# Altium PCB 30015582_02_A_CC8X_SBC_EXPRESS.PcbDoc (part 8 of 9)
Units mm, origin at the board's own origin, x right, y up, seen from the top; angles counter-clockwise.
Board outline 87 x 63 mm, 6 copper layers (Top Layer-L1, GND Plane-L2, Signal-L3, PWR/Signal-L4, GND Plane-L5, Bottom Layer-L6), stack 1.172 mm thick; 169 components, 171 nets, 693 pads, 391 vias.
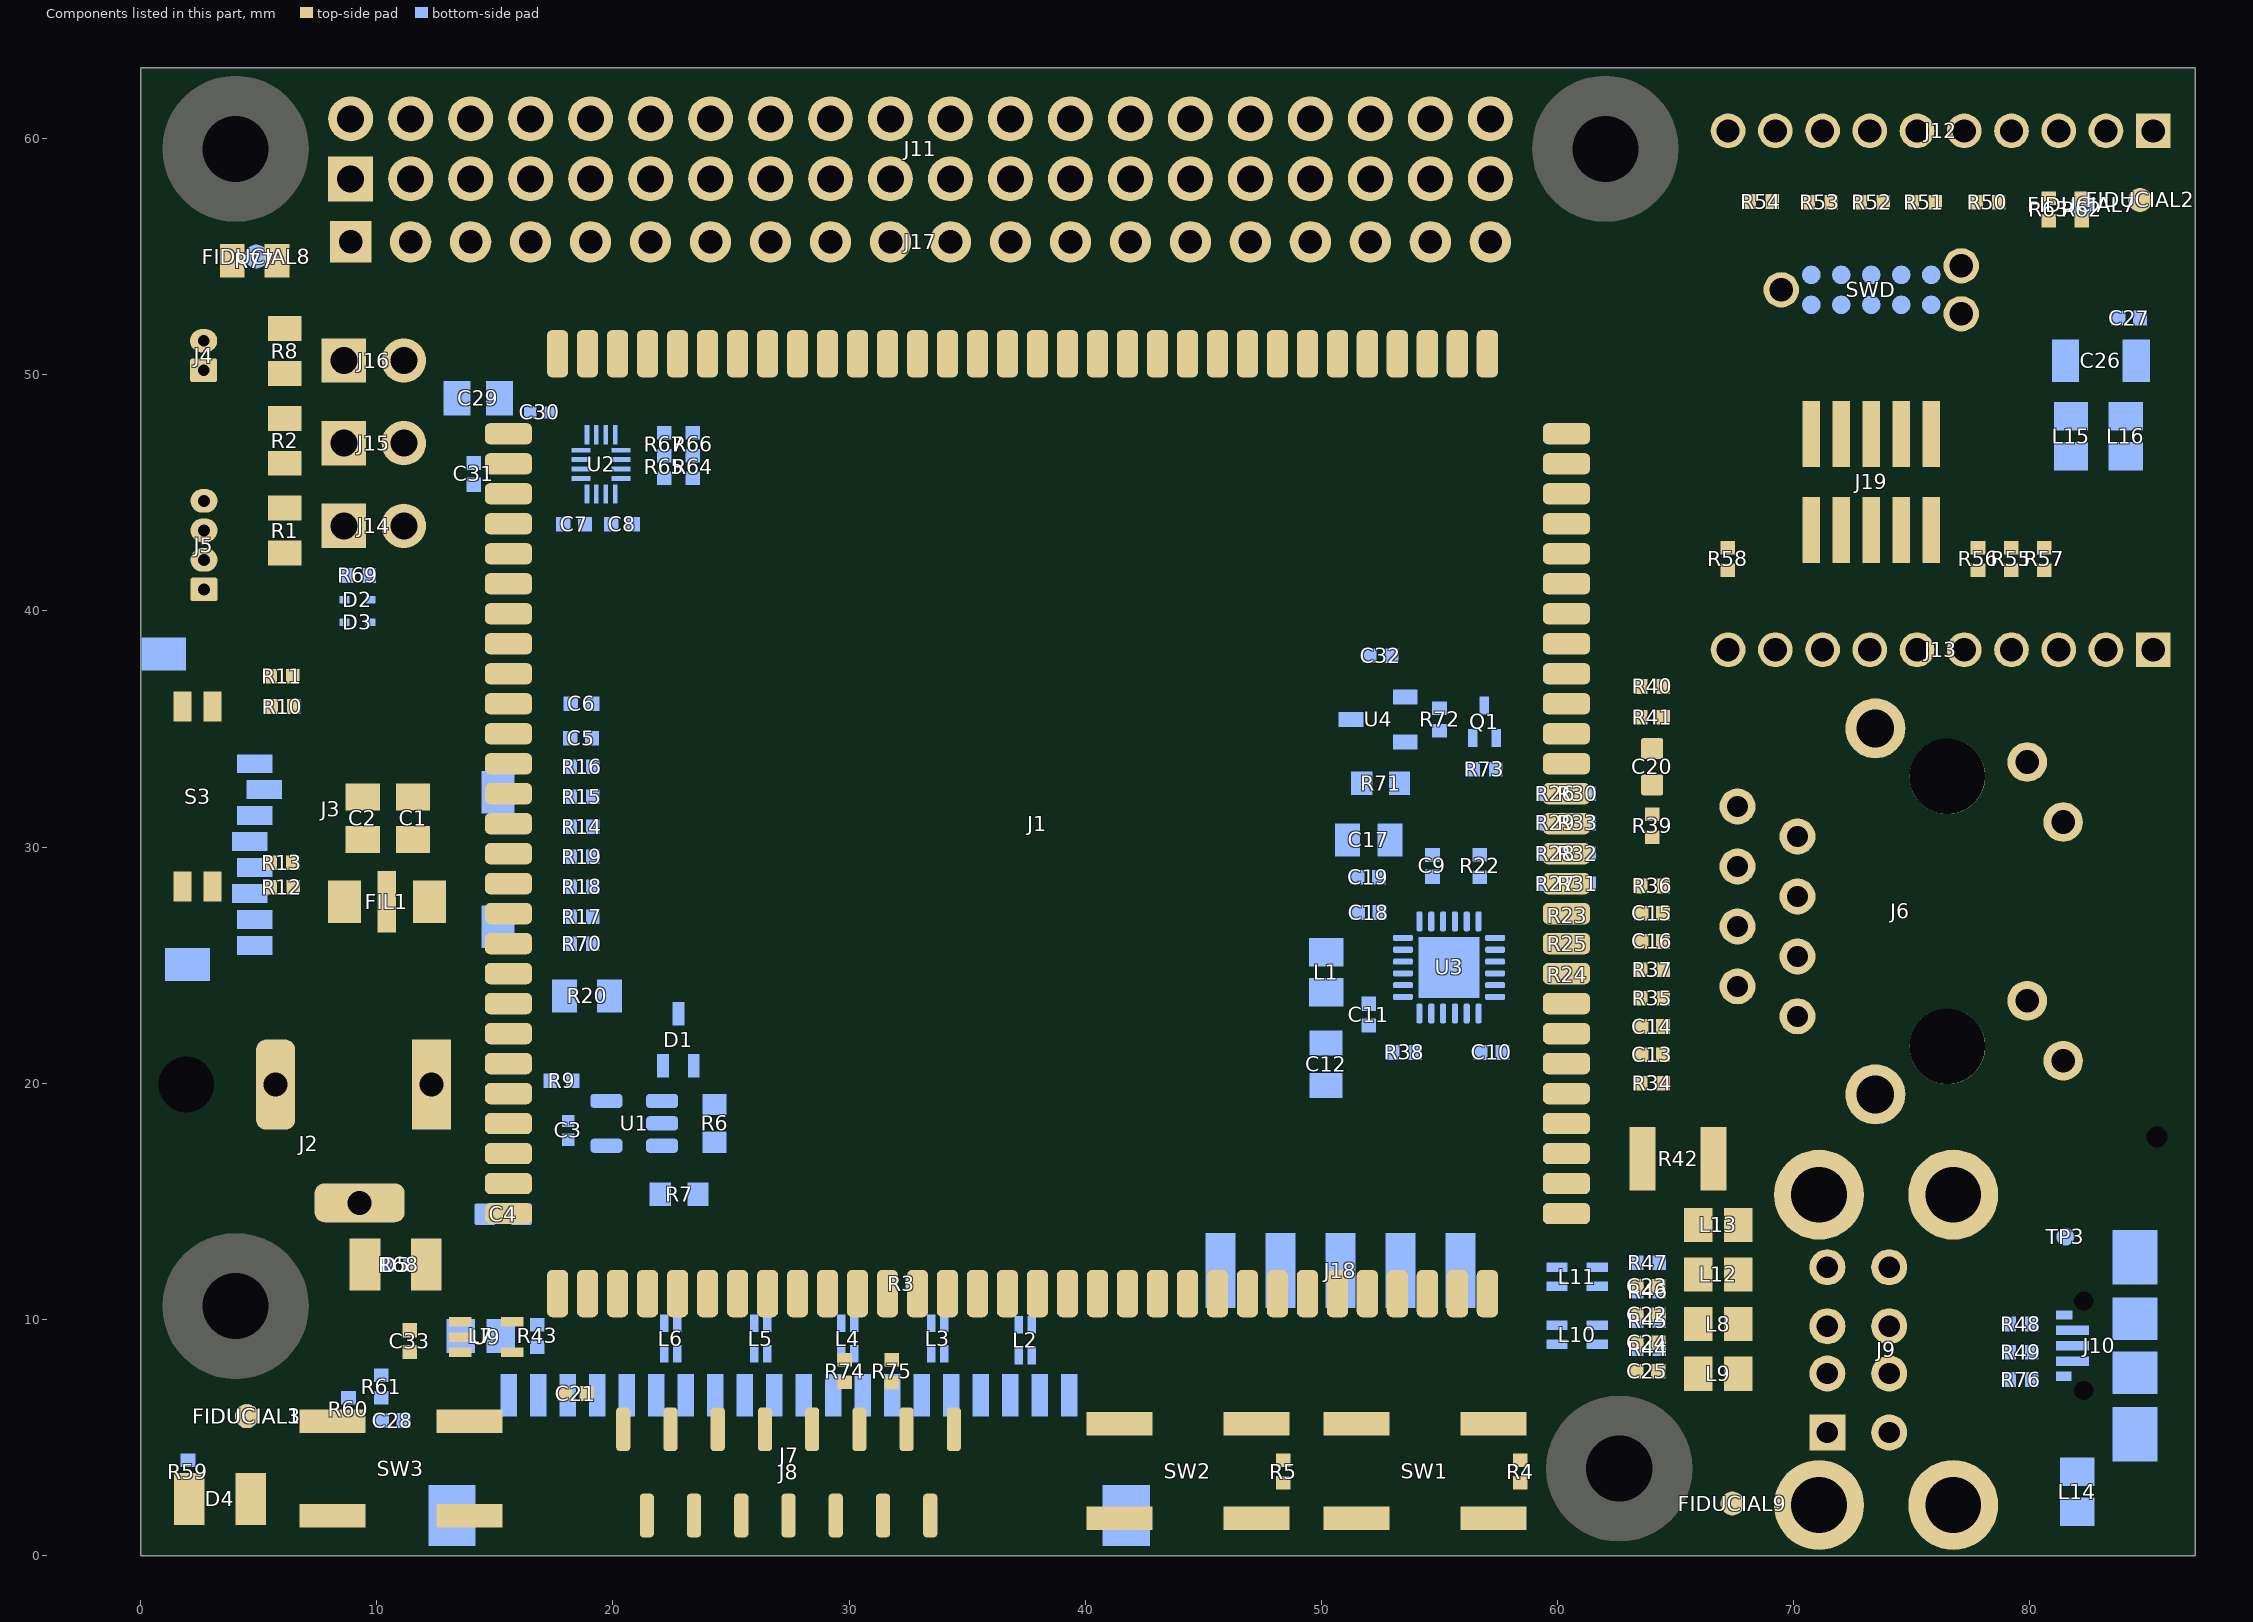
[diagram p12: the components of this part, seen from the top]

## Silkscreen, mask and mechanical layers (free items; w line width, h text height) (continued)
Resistive Material Bottom:
  circle w0.1: c54.7,69.6 r5
  region: 175.78,120.65 211.843,120.65 211.843,120.396 175.78,120.396
  region: 113.371,120.65 149.094,120.65 149.094,120.396 113.371,120.396
  region: 121.517,125.379 165.046,125.379 165.046,125.126 121.517,125.126
  region: 128.857,134.838 173.023,134.838 173.023,134.584 128.857,134.584
  region: 108.28,254.166 156.434,254.166 156.434,253.913 108.28,253.913
  region: 0,34.4 4.9,34.4 8.3,37.8 8.3,49.6 59.6,49.6 64.5,54.5 87,54.5 87,62.9 0,62.9
  region: 63.9,0.3 63.9,3.674 cw(c66.618,3.674) 64.696,5.596 65.4,6.3 65.4,11.074 ccw(c62.682,11.074) 64.604,12.996 64.4,13.2 cw(c65.366,14.166) 64,14.166 64,16.274 cw(c66.718,16.274) 64.796,18.196 64.9,18.3 ccw(c63.21,18.3) 64.405,19.495 62.496,21.404 cw(c64.418,23.326) 61.7,23.326 61.7,32.9 cw(c63.39,32.9) 62.195,34.095 62.5,34.4 62.5,35.234 ccw(c61.134,35.234) 62.1,36.2 62.1,40.074 cw(c64.818,40.074) 62.896,41.996 65.1,44.2 87,44.2 87,14.6 83.7,14.6 83.7,14.19 cw(c81.31,14.19) 83,12.5 81.796,11.296 cw(c79.874,13.218) 79.874,10.5 79.7,10.5 79.7,8.683 ccw(c80.383,8.683) 79.9,8.2 ccw(c80.383,8.683) 80.383,8 80.4,8 cw(c80.4,7.276) 80.912,7.788 82.6,6.1 cw(c81.393,4.893) 83.1,4.893 83.1,4.8 cw(c81.651,3.351) 83.7,3.351 83.7,0.541 cw(c83.359,0.541) 83.6,0.3
  region: 0.7,22.974 cw(c3.418,22.974) 1.496,24.896 2.804,26.204 cw(c4.726,24.282) 4.726,27 6.574,27 cw(c6.574,24.282) 8.496,26.204 8.588,26.112 ccw(c9.1,26.624) 9.1,25.9 ccw(c9.1,26.866) 9.783,26.183 10.1,26.5 cw(c11.066,25.534) 11.066,26.9 13.8,26.9 cw(c13.8,25.21) 14.995,26.405 16.704,24.696 cw(c14.782,22.774) 17.5,22.774 17.5,22.7 cw(c15.81,21.01) 18.2,21.01 18.2,18.926 cw(c15.482,18.926) 17.404,17.004 16.3,15.9 16.3,14.026 cw(c13.582,14.026) 15.504,12.104 14.107,10.707 cw(c12.4,12.414) 12.4,10 12.196,9.796 cw(c10.274,11.718) 10.274,9 8.626,9 cw(c8.626,11.718) 6.704,9.796 1.496,15.004 cw(c3.418,16.926) 0.7,16.926
  text "H" at 85.2,278.446 h4.63
  text "i" at 87.607,278.446 h4.63
  text "E" at 89.38,278.446 h4.63
  text "n" at 91.28,278.446 h4.63
  text "r" at 93.307,278.446 h4.63
  text "i" at 94.658,278.446 h4.63
  text "q" at 95.545,278.446 h4.63
  text "u" at 97.572,278.446 h4.63
  text "e" at 99.599,278.446 h4.63
  text "," at 101.541,278.446 h4.63
  text "I" at 85.2,268.987 h4.63
  text "c" at 87.058,268.987 h4.63
  text "l" at 88.705,268.987 h4.63
  text "e" at 89.591,268.987 h4.63
  text "a" at 91.534,268.987 h4.63
  text "r" at 93.392,268.987 h4.63
  text "l" at 94.743,268.987 h4.63
  text "y" at 95.63,268.987 h4.63
  text "u" at 98.248,268.987 h4.63
  text "n" at 100.274,268.987 h4.63
  text "d" at 102.301,268.987 h4.63
  text "e" at 104.328,268.987 h4.63
  text "r" at 106.27,268.987 h4.63
  text "s" at 107.622,268.987 h4.63
  text "t" at 109.142,268.987 h4.63
  text "a" at 110.451,268.987 h4.63
  text "n" at 112.309,268.987 h4.63
  text "d" at 114.335,268.987 h4.63
  text "y" at 117.207,268.987 h4.63
  text "o" at 118.98,268.987 h4.63
  text "u" at 121.049,268.987 h4.63
  text "r" at 123.076,268.987 h4.63
  text "p" at 125.314,268.987 h4.63
  text "o" at 127.299,268.987 h4.63
  text "i" at 129.368,268.987 h4.63
  text "n" at 130.254,268.987 h4.63
  text "t" at 132.281,268.987 h4.63
  text "a" at 134.477,268.987 h4.63
  text "n" at 136.335,268.987 h4.63
  text "d" at 138.362,268.987 h4.63
  text "w" at 141.233,268.987 h4.63
  text "e" at 144.02,268.987 h4.63
  text "w" at 146.807,268.987 h4.63
  text "i" at 149.594,268.987 h4.63
  text "l" at 150.48,268.987 h4.63
  text "l" at 151.367,268.987 h4.63
  text "s" at 153.14,268.987 h4.63
  text "e" at 154.661,268.987 h4.63
  text "e" at 156.561,268.987 h4.63
  text "w" at 159.39,268.987 h4.63
  text "h" at 162.177,268.987 h4.63
  text "a" at 164.204,268.987 h4.63
  text "t" at 166.019,268.987 h4.63
  text "w" at 168.173,268.987 h4.63
  text "e" at 170.96,268.987 h4.63
  text "c" at 173.789,268.987 h4.63
  text "a" at 175.435,268.987 h4.63
  text "n" at 177.293,268.987 h4.63
  text "d" at 180.165,268.987 h4.63
  text "o" at 182.191,268.987 h4.63
  text "a" at 185.147,268.987 h4.63
  text "s" at 186.963,268.987 h4.63
  text "a" at 189.37,268.987 h4.63
  text "t" at 192.114,268.987 h4.63
  text "r" at 193.381,268.987 h4.63
  text "a" at 194.732,268.987 h4.63
  text "d" at 196.59,268.987 h4.63
  text "e" at 198.617,268.987 h4.63
  text "o" at 200.559,268.987 h4.63
  text "f" at 202.586,268.987 h4.63
  text "f" at 203.769,268.987 h4.63
  text "." at 204.951,268.987 h4.63
  text "H" at 85.2,264.258 h4.63
  text "e" at 87.607,264.258 h4.63
  text "r" at 89.549,264.258 h4.63
  text "e" at 90.9,264.258 h4.63
  text "s" at 93.73,264.258 h4.63
  text "o" at 95.207,264.258 h4.63
  text "m" at 97.234,264.258 h4.63
  text "e" at 100.359,264.258 h4.63
  text "n" at 103.188,264.258 h4.63
  text "o" at 105.173,264.258 h4.63
  text "t" at 107.242,264.258 h4.63
  text "e" at 108.551,264.258 h4.63
  text "s" at 110.451,264.258 h4.63
  text ":" at 111.971,264.258 h4.63
  text "" at 91.564,259.318 h4.59
  text "P" at 97.928,259.318 h4.63
  text "l" at 99.955,259.318 h4.63
  text "e" at 100.841,259.318 h4.63
  text "a" at 102.784,259.318 h4.63
  text "s" at 104.642,259.318 h4.63
  text "e" at 106.12,259.318 h4.63
  text "d" at 108.949,259.318 h4.63
  text "o" at 110.976,259.318 h4.63
  text "n" at 113.045,259.318 h4.63
  text "" at 115.071,259.318 h4.63
  text "t" at 116,259.318 h4.63
  text "c" at 118.196,259.318 h4.63
  text "o" at 119.801,259.318 h4.63
  text "n" at 121.87,259.318 h4.63
  text "s" at 123.896,259.318 h4.63
  text "i" at 125.417,259.318 h4.63
  text "d" at 126.303,259.318 h4.63
  text "e" at 128.33,259.318 h4.63
  text "r" at 130.272,259.318 h4.63
  text "S" at 132.51,259.318 h4.63
  text "W" at 134.242,259.318 h4.63
  text "D" at 137.704,259.318 h4.63
  text "a" at 140.955,259.318 h4.63
  text "s" at 142.813,259.318 h4.63
  text "a" at 145.22,259.318 h4.63
  text "T" at 147.965,259.318 h4.63
  text "H" at 149.865,259.318 h4.63
  text "T" at 152.272,259.318 h4.63
  text "p" at 155.016,259.318 h4.63
  text "a" at 157.043,259.318 h4.63
  text "r" at 158.901,259.318 h4.63
  text "t" at 160.252,259.318 h4.63
  text "." at 161.561,259.318 h4.63
  text "T" at 163.419,259.318 h4.63
  text "h" at 165.319,259.318 h4.63
  text "i" at 167.346,259.318 h4.63
  text "s" at 168.233,259.318 h4.63
  text "s" at 170.598,259.318 h4.63
  text "h" at 172.118,259.318 h4.63
  text "o" at 174.145,259.318 h4.63
  text "u" at 176.214,259.318 h4.63
  text "l" at 178.24,259.318 h4.63
  text "d" at 179.127,259.318 h4.63
  text "b" at 182.041,259.318 h4.63
  text "e" at 184.025,259.318 h4.63
  text "t" at 186.854,259.318 h4.63
  text "h" at 188.163,259.318 h4.63
  text "e" at 190.19,259.318 h4.63
  text "f" at 193.019,259.318 h4.63
  text "o" at 194.159,259.318 h4.63
  text "o" at 196.186,259.318 h4.63
  text "t" at 198.255,259.318 h4.63
  text "p" at 199.564,259.318 h4.63
  text "r" at 201.591,259.318 h4.63
  text "i" at 202.942,259.318 h4.63
  text "n" at 203.829,259.318 h4.63
  text "t" at 205.856,259.318 h4.63
  text "f" at 208.051,259.318 h4.63
  text "o" at 209.192,259.318 h4.63
  text "r" at 211.261,259.318 h4.63
  text "t" at 213.456,259.318 h4.63
  text "h" at 214.765,259.318 h4.63
  text "i" at 216.792,259.318 h4.63
  text "s" at 217.679,259.318 h4.63
  text "k" at 220.086,259.318 h4.63
  text "i" at 221.859,259.318 h4.63
  text "n" at 222.746,259.318 h4.63
  text "d" at 224.773,259.318 h4.63
  text "o" at 227.644,259.318 h4.63
  text "f" at 229.713,259.318 h4.63
  text "c" at 97.928,254.588 h4.63
  text "a" at 99.575,254.588 h4.63
  text "b" at 101.433,254.588 h4.63
  text "l" at 103.459,254.588 h4.63
  text "e" at 104.346,254.588 h4.63
  text ":" at 106.289,254.588 h4.63
  text "h" at 108.28,254.588 h4.63
  text "t" at 110.307,254.588 h4.63
  text "t" at 111.574,254.588 h4.63
  text "p" at 112.882,254.588 h4.63
  text ":" at 114.909,254.588 h4.63
  text "/" at 115.923,254.588 h4.63
  text "/" at 117.443,254.588 h4.63
  text "w" at 118.921,254.588 h4.63
  text "w" at 121.708,254.588 h4.63
  text "w" at 124.452,254.588 h4.63
  text "." at 127.239,254.588 h4.63
  text "t" at 128.21,254.588 h4.63
  text "a" at 129.519,254.588 h4.63
  text "g" at 131.377,254.588 h4.63
  text "-" at 133.312,254.588 h4.63
  text "c" at 134.499,254.588 h4.63
  text "o" at 136.146,254.588 h4.63
  text "n" at 138.215,254.588 h4.63
  text "n" at 140.2,254.588 h4.63
  text "e" at 142.227,254.588 h4.63
  text "c" at 144.169,254.588 h4.63
  text "t" at 145.816,254.588 h4.63
  text "." at 147.125,254.588 h4.63
  text "c" at 148.096,254.588 h4.63
  text "o" at 149.701,254.588 h4.63
  text "m" at 151.77,254.588 h4.63
  text "/" at 154.852,254.588 h4.63
  text "" at 91.564,249.69 h4.59
  text "J" at 97.928,249.69 h4.63
  text "1" at 99.152,249.69 h4.63
  text "4" at 101.137,249.69 h4.63
  text "/" at 103.122,249.69 h4.63
  text "J" at 104.642,249.69 h4.63
  text "1" at 105.824,249.69 h4.63
  text "5" at 107.809,249.69 h4.63
  text "/" at 109.751,249.69 h4.63
  text "J" at 111.271,249.69 h4.63
  text "1" at 112.496,249.69 h4.63
  text "6" at 114.438,249.69 h4.63
  text "s" at 117.309,249.69 h4.63
  text "h" at 118.829,249.69 h4.63
  text "o" at 120.814,249.69 h4.63
  text "u" at 122.883,249.69 h4.63
  text "l" at 124.91,249.69 h4.63
  text "d" at 125.797,249.69 h4.63
  text "a" at 128.71,249.69 h4.63
  text "l" at 130.568,249.69 h4.63
  text "s" at 131.455,249.69 h4.63
  text "o" at 132.975,249.69 h4.63
  text "n" at 135.888,249.69 h4.63
  text "o" at 137.915,249.69 h4.63
  text "t" at 139.942,249.69 h4.63
  text "b" at 142.138,249.69 h4.63
  text "e" at 144.165,249.69 h4.63
  text "c" at 146.994,249.69 h4.63
  text "o" at 148.598,249.69 h4.63
  text "n" at 150.667,249.69 h4.63
  text "s" at 152.694,249.69 h4.63
  text "i" at 154.214,249.69 h4.63
  text "d" at 155.101,249.69 h4.63
  text "e" at 157.128,249.69 h4.63
  text "r" at 159.07,249.69 h4.63
  text "e" at 160.379,249.69 h4.63
  text "d" at 162.321,249.69 h4.63
  text "a" at 165.235,249.69 h4.63
  text "s" at 167.093,249.69 h4.63
  text "T" at 169.5,249.69 h4.63
  text "H" at 171.4,249.69 h4.63
  text "T" at 173.765,249.69 h4.63
  text "p" at 176.551,249.69 h4.63
  text "a" at 178.578,249.69 h4.63
  text "r" at 180.436,249.69 h4.63
  text "t" at 181.787,249.69 h4.63
  text "s" at 183.054,249.69 h4.63
  text "." at 184.574,249.69 h4.63
  text "I" at 186.432,249.69 h4.63
  text "f" at 187.403,249.69 h4.63
  text "t" at 189.472,249.69 h4.63
  text "h" at 190.781,249.69 h4.63
  text "e" at 192.808,249.69 h4.63
  text "y" at 194.75,249.69 h4.63
  text "a" at 197.368,249.69 h4.63
  text "r" at 199.226,249.69 h4.63
  text "e" at 200.578,249.69 h4.63
  text "p" at 203.364,249.69 h4.63
  text "o" at 205.391,249.69 h4.63
  text "p" at 207.46,249.69 h4.63
  text "u" at 209.487,249.69 h4.63
  text "l" at 211.514,249.69 h4.63
  text "a" at 212.401,249.69 h4.63
  text "t" at 214.259,249.69 h4.63
  text "e" at 215.568,249.69 h4.63
  text "d" at 217.51,249.69 h4.63
  text "," at 219.537,249.69 h4.63
  text "i" at 221.352,249.69 h4.63
  text "t" at 222.239,249.69 h4.63
  text "w" at 224.393,249.69 h4.63
  text "i" at 227.18,249.69 h4.63
  text "l" at 228.066,249.69 h4.63
  text "l" at 228.953,249.69 h4.63
  text "a" at 97.928,244.961 h4.63
  text "l" at 99.786,244.961 h4.63
  text "w" at 100.673,244.961 h4.63
  text "a" at 103.459,244.961 h4.63
  text "y" at 105.317,244.961 h4.63
  text "s" at 107.091,244.961 h4.63
  text "b" at 109.455,244.961 h4.63
  text "e" at 111.482,244.961 h4.63
  text "h" at 114.311,244.961 h4.63
  text "a" at 116.338,244.961 h4.63
  text "n" at 118.196,244.961 h4.63
  text "d" at 120.223,244.961 h4.63
  text "s" at 123.136,244.961 h4.63
  text "o" at 124.614,244.961 h4.63
  text "l" at 126.683,244.961 h4.63
  text "d" at 127.57,244.961 h4.63
  text "e" at 129.597,244.961 h4.63
  text "r" at 131.539,244.961 h4.63
  text "i" at 132.89,244.961 h4.63
  text "n" at 133.777,244.961 h4.63
  text "g" at 135.804,244.961 h4.63
  text "." at 137.62,244.961 h4.63
  text "T" at 139.435,244.961 h4.63
  text "h" at 141.336,244.961 h4.63
  text "e" at 143.362,244.961 h4.63
  text "j" at 146.191,244.961 h4.63
  text "u" at 147.12,244.961 h4.63
  text "m" at 149.147,244.961 h4.63
  text "p" at 152.272,244.961 h4.63
  text "e" at 154.256,244.961 h4.63
  text "r" at 156.199,244.961 h4.63
  text "s" at 157.55,244.961 h4.63
  text "a" at 159.957,244.961 h4.63
  text "r" at 161.815,244.961 h4.63
  text "e" at 163.124,244.961 h4.63
  text "t" at 165.953,244.961 h4.63
  text "h" at 167.262,244.961 h4.63
  text "e" at 169.289,244.961 h4.63
  text "r" at 171.189,244.961 h4.63
  text "e" at 172.54,244.961 h4.63
  text "o" at 175.327,244.961 h4.63
  text "n" at 177.396,244.961 h4.63
  text "l" at 179.423,244.961 h4.63
  text "y" at 180.309,244.961 h4.63
  text "f" at 182.927,244.961 h4.63
  text "o" at 184.11,244.961 h4.63
  text "r" at 186.179,244.961 h4.63
  text "d" at 188.417,244.961 h4.63
  text "e" at 190.444,244.961 h4.63
  text "b" at 192.386,244.961 h4.63
  text "u" at 194.413,244.961 h4.63
  text "g" at 196.44,244.961 h4.63
  text "g" at 198.255,244.961 h4.63
  text "i" at 200.071,244.961 h4.63
  text "n" at 200.958,244.961 h4.63
  text "g" at 202.984,244.961 h4.63
  text "p" at 205.687,244.961 h4.63
  text "u" at 207.714,244.961 h4.63
  text "r" at 209.74,244.961 h4.63
  text "p" at 211.092,244.961 h4.63
  text "o" at 213.118,244.961 h4.63
  text "s" at 215.188,244.961 h4.63
  text "e" at 216.665,244.961 h4.63
  text "s" at 218.608,244.961 h4.63
  text "." at 220.128,244.961 h4.63
  text "" at 91.564,240.021 h4.59
  text "C" at 97.928,240.021 h4.63
  text "o" at 99.997,240.021 h4.63
  text "n" at 102.066,240.021 h4.63
  text "c" at 104.093,240.021 h4.63
  text "e" at 105.74,240.021 h4.63
  text "r" at 107.682,240.021 h4.63
  text "n" at 109.033,240.021 h4.63
  text "i" at 111.06,240.021 h4.63
  text "n" at 111.947,240.021 h4.63
  text "g" at 113.974,240.021 h4.63
  text "p" at 116.676,240.021 h4.63
  text "a" at 118.703,240.021 h4.63
  text "r" at 120.561,240.021 h4.63
  text "t" at 121.912,240.021 h4.63
  text "s" at 123.221,240.021 h4.63
  text "b" at 125.585,240.021 h4.63
  text "e" at 127.612,240.021 h4.63
  text "t" at 129.555,240.021 h4.63
  text "w" at 130.821,240.021 h4.63
  text "e" at 133.608,240.021 h4.63
  text "e" at 135.551,240.021 h4.63
  text "n" at 137.493,240.021 h4.63
  text "J" at 140.322,240.021 h4.63
  text "1" at 141.547,240.021 h4.63
  text "2" at 143.531,240.021 h4.63
  text "&" at 146.36,240.021 h4.63
  text "J" at 149.907,240.021 h4.63
  text "1" at 151.132,240.021 h4.63
  text "3" at 153.074,240.021 h4.63
  text "," at 155.059,240.021 h4.63
  text "a" at 156.917,240.021 h4.63
  text "n" at 158.775,240.021 h4.63
  text "d" at 160.801,240.021 h4.63
  text "e" at 163.673,240.021 h4.63
  text "s" at 165.615,240.021 h4.63
  text "p" at 167.135,240.021 h4.63
  text "e" at 169.162,240.021 h4.63
  text "c" at 171.104,240.021 h4.63
  text "i" at 172.751,240.021 h4.63
  text "a" at 173.638,240.021 h4.63
  text "l" at 175.496,240.021 h4.63
  text "l" at 176.382,240.021 h4.63
  text "y" at 177.227,240.021 h4.63
  text "t" at 179.887,240.021 h4.63
  text "h" at 181.196,240.021 h4.63
  text "e" at 183.181,240.021 h4.63
  text "p" at 186.01,240.021 h4.63
  text "a" at 188.037,240.021 h4.63
  text "s" at 189.895,240.021 h4.63
  text "s" at 191.415,240.021 h4.63
  text "i" at 192.935,240.021 h4.63
  text "v" at 193.822,240.021 h4.63
  text "e" at 195.553,240.021 h4.63
  text "," at 197.495,240.021 h4.63
  text "t" at 199.794,240.021 h4.63
  text "h" at 201.103,240.021 h4.63
  text "e" at 203.129,240.021 h4.63
  text "y" at 205.072,240.021 h4.63
  text "c" at 207.69,240.021 h4.63
  text "a" at 209.337,240.021 h4.63
  text "n" at 211.194,240.021 h4.63
  text "b" at 214.108,240.021 h4.63
  text "e" at 216.135,240.021 h4.63
  text "p" at 218.964,240.021 h4.63
  text "l" at 220.991,240.021 h4.63
  text "a" at 221.877,240.021 h4.63
  text "c" at 223.693,240.021 h4.63
  text "e" at 225.298,240.021 h4.63
  text "d" at 227.24,240.021 h4.63
  text "o" at 230.154,240.021 h4.63
  text "n" at 232.223,240.021 h4.63
  text "t" at 235.094,240.021 h4.63
  text "o" at 236.403,240.021 h4.63
  text "p" at 238.472,240.021 h4.63
  text "s" at 97.928,235.291 h4.63
  text "i" at 99.448,235.291 h4.63
  text "d" at 100.335,235.291 h4.63
  text "e" at 102.362,235.291 h4.63
  text "a" at 105.191,235.291 h4.63
  text "p" at 107.049,235.291 h4.63
  text "a" at 109.075,235.291 h4.63
  text "r" at 110.933,235.291 h4.63
  text "t" at 112.285,235.291 h4.63
  text "t" at 114.438,235.291 h4.63
  text "h" at 115.747,235.291 h4.63
  text "e" at 117.774,235.291 h4.63
  text "b" at 120.603,235.291 h4.63
  text "i" at 122.63,235.291 h4.63
  text "g" at 123.516,235.291 h4.63
  text "c" at 126.219,235.291 h4.63
  text "a" at 127.866,235.291 h4.63
  text "p" at 129.724,235.291 h4.63
  text "a" at 132.637,235.291 h4.63
  text "n" at 134.495,235.291 h4.63
  text "d" at 136.522,235.291 h4.63
  text "i" at 139.435,235.291 h4.63
  text "n" at 140.28,235.291 h4.63
  text "d" at 142.307,235.291 h4.63
  text "u" at 144.334,235.291 h4.63
  text "c" at 146.36,235.291 h4.63
  text "t" at 148.007,235.291 h4.63
  text "o" at 149.316,235.291 h4.63
  text "r" at 151.385,235.291 h4.63
  text "s" at 152.736,235.291 h4.63
  text "(" at 155.143,235.291 h4.63
  text "C" at 156.325,235.291 h4.63
  text "2" at 158.352,235.291 h4.63
  text "6" at 160.295,235.291 h4.63
  text "/" at 162.279,235.291 h4.63
  text "L" at 163.757,235.291 h4.63
  text "1" at 165.404,235.291 h4.63
  text "5" at 167.346,235.291 h4.63
  text "/" at 169.331,235.291 h4.63
  text "L" at 170.809,235.291 h4.63
  text "1" at 172.456,235.291 h4.63
  text "6" at 174.398,235.291 h4.63
  text ")" at 176.382,235.291 h4.63
  text "." at 177.565,235.291 h4.63
  text "T" at 179.423,235.291 h4.63
  text "r" at 181.323,235.291 h4.63
  text "y" at 182.632,235.291 h4.63
  text "t" at 185.292,235.291 h4.63
  text "o" at 186.559,235.291 h4.63
  text "p" at 189.515,235.291 h4.63
  text "l" at 191.541,235.291 h4.63
  text "a" at 192.428,235.291 h4.63
  text "c" at 194.286,235.291 h4.63
  text "e" at 195.891,235.291 h4.63
  text "t" at 198.72,235.291 h4.63
  text "h" at 200.029,235.291 h4.63
  text "e" at 202.055,235.291 h4.63
  text "s" at 203.998,235.291 h4.63
  text "e" at 205.476,235.291 h4.63
  text "b" at 208.305,235.291 h4.63
  text "i" at 210.332,235.291 h4.63
  text "g" at 211.218,235.291 h4.63
  text "c" at 213.921,235.291 h4.63
  text "o" at 215.525,235.291 h4.63
  text "m" at 217.552,235.291 h4.63
  text "p" at 220.677,235.291 h4.63
  text "o" at 222.704,235.291 h4.63
  text "n" at 224.73,235.291 h4.63
  text "e" at 226.757,235.291 h4.63
  text "n" at 228.7,235.291 h4.63
  text "t" at 230.726,235.291 h4.63
  text "s" at 232.035,235.291 h4.63
  text "i" at 234.442,235.291 h4.63
  text "n" at 235.329,235.291 h4.63
  text "t" at 97.928,230.562 h4.63
  text "h" at 99.237,230.562 h4.63
  text "e" at 101.264,230.562 h4.63
  text "m" at 104.051,230.562 h4.63
  text "i" at 107.175,230.562 h4.63
  text "d" at 108.062,230.562 h4.63
  text "d" at 110.089,230.562 h4.63
  text "l" at 112.116,230.562 h4.63
  text "e" at 113.002,230.562 h4.63
  text "b" at 115.831,230.562 h4.63
  text "e" at 117.858,230.562 h4.63
  text "t" at 119.801,230.562 h4.63
  text "w" at 121.067,230.562 h4.63
  text "e" at 123.854,230.562 h4.63
  text "e" at 125.754,230.562 h4.63
  text "n" at 127.697,230.562 h4.63
  text "J" at 130.61,230.562 h4.63
  text "1" at 131.835,230.562 h4.63
  text "2" at 133.777,230.562 h4.63
  text "&" at 136.648,230.562 h4.63
  text "J" at 140.111,230.562 h4.63
  text "1" at 141.336,230.562 h4.63
  text "3" at 143.32,230.562 h4.63
  text "." at 145.305,230.562 h4.63
  text "" at 91.564,225.622 h4.59
  text "R" at 97.928,225.622 h4.63
  text "4" at 100.039,225.622 h4.63
  text "2" at 102.024,225.622 h4.63
  text "c" at 104.853,225.622 h4.63
  text "a" at 106.5,225.622 h4.63
  text "n" at 108.358,225.622 h4.63
  text "a" at 111.271,225.622 h4.63
  text "l" at 113.129,225.622 h4.63
  text "s" at 114.016,225.622 h4.63
  text "o" at 115.494,225.622 h4.63
  text "b" at 118.449,225.622 h4.63
  text "e" at 120.476,225.622 h4.63
  text "p" at 123.263,225.622 h4.63
  text "l" at 125.29,225.622 h4.63
  text "a" at 126.177,225.622 h4.63
  text "c" at 128.035,225.622 h4.63
  text "e" at 129.681,225.622 h4.63
  text "d" at 131.624,225.622 h4.63
  text "o" at 134.495,225.622 h4.63
  text "n" at 136.564,225.622 h4.63
  text "t" at 139.478,225.622 h4.63
  text "h" at 140.744,225.622 h4.63
  text "e" at 142.771,225.622 h4.63
  text "T" at 145.6,225.622 h4.63
  text "O" at 147.5,225.622 h4.63
  text "P" at 150.034,225.622 h4.63
  text "s" at 152.947,225.622 h4.63
  text "i" at 154.468,225.622 h4.63
  text "d" at 155.354,225.622 h4.63
  text "e" at 157.381,225.622 h4.63
  text "," at 159.323,225.622 h4.63
  text "I" at 161.139,225.622 h4.63
  text "g" at 162.997,225.622 h4.63
  text "u" at 164.813,225.622 h4.63
  text "e" at 166.84,225.622 h4.63
  text "s" at 168.782,225.622 h4.63
  text "s" at 170.302,225.622 h4.63
  text "." at 171.822,225.622 h4.63
  text "" at 91.564,220.724 h4.59
  text "C" at 97.928,220.724 h4.63
  text "o" at 99.997,220.724 h4.63
  text "n" at 102.066,220.724 h4.63
  text "c" at 104.093,220.724 h4.63
  text "e" at 105.74,220.724 h4.63
  text "r" at 107.682,220.724 h4.63
  text "n" at 109.033,220.724 h4.63
  text "i" at 111.06,220.724 h4.63
  text "n" at 111.947,220.724 h4.63
  text "g" at 113.974,220.724 h4.63
  text "p" at 116.676,220.724 h4.63
  text "a" at 118.703,220.724 h4.63
  text "r" at 120.561,220.724 h4.63
  text "t" at 121.912,220.724 h4.63
  text "s" at 123.221,220.724 h4.63
  text "a" at 125.585,220.724 h4.63
  text "r" at 127.443,220.724 h4.63
  text "o" at 128.795,220.724 h4.63
  text "u" at 130.864,220.724 h4.63
  text "n" at 132.89,220.724 h4.63
  text "d" at 134.917,220.724 h4.63
  text "J" at 137.831,220.724 h4.63
  text "6" at 139.013,220.724 h4.63
  text "," at 140.955,220.724 h4.63
  text "p" at 142.813,220.724 h4.63
  text "l" at 144.84,220.724 h4.63
  text "e" at 145.727,220.724 h4.63
  text "a" at 147.669,220.724 h4.63
  text "s" at 149.527,220.724 h4.63
  text "e" at 151.047,220.724 h4.63
  text "k" at 153.834,220.724 h4.63
  text "e" at 155.608,220.724 h4.63
  text "e" at 157.508,220.724 h4.63
  text "p" at 159.45,220.724 h4.63
  text "C" at 162.364,220.724 h4.63
  text "1" at 164.433,220.724 h4.63
  text "3" at 166.375,220.724 h4.63
  text "/" at 168.36,220.724 h4.63
  text "C" at 169.838,220.724 h4.63
  text "1" at 171.907,220.724 h4.63
  text "4" at 173.849,220.724 h4.63
  text "/" at 175.834,220.724 h4.63
  text "C" at 177.354,220.724 h4.63
  text "1" at 179.38,220.724 h4.63
  text "5" at 181.365,220.724 h4.63
  text "/" at 183.307,220.724 h4.63
  text "C" at 184.828,220.724 h4.63
  text "1" at 186.897,220.724 h4.63
  text "6" at 188.839,220.724 h4.63
  text "o" at 191.668,220.724 h4.63
  text "n" at 193.737,220.724 h4.63
  text "t" at 196.651,220.724 h4.63
  text "h" at 197.96,220.724 h4.63
  text "e" at 199.986,220.724 h4.63
  text "b" at 203.273,220.724 h4.63
  text "o" at 205.299,220.724 h4.63
  text "t" at 207.368,220.724 h4.63
  text "t" at 208.635,220.724 h4.63
  text "o" at 209.944,220.724 h4.63
  text "m" at 211.971,220.724 h4.63
  text "s" at 215.94,220.724 h4.63
  text "i" at 217.46,220.724 h4.63
  text "d" at 218.347,220.724 h4.63
  text "e" at 220.374,220.724 h4.63
  text "." at 222.316,220.724 h4.63
  text "T" at 224.174,220.724 h4.63
  text "h" at 226.032,220.724 h4.63
  text "e" at 228.059,220.724 h4.63
  text "s" at 230.001,220.724 h4.63
  text "e" at 231.521,220.724 h4.63
  text "p" at 97.928,215.995 h4.63
  text "a" at 99.955,215.995 h4.63
  text "r" at 101.813,215.995 h4.63
  text "t" at 103.164,215.995 h4.63
  text "s" at 104.473,215.995 h4.63
  text "w" at 106.88,215.995 h4.63
  text "i" at 109.667,215.995 h4.63
  text "l" at 110.553,215.995 h4.63
  text "l" at 111.44,215.995 h4.63
  text "b" at 113.213,215.995 h4.63
  text "e" at 115.198,215.995 h4.63
  text "m" at 117.985,215.995 h4.63
  text "o" at 121.11,215.995 h4.63
  text "s" at 123.179,215.995 h4.63
  text "t" at 124.657,215.995 h4.63
  text "c" at 126.852,215.995 h4.63
  text "e" at 128.457,215.995 h4.63
  text "r" at 130.399,215.995 h4.63
  text "t" at 131.75,215.995 h4.63
  text "a" at 133.059,215.995 h4.63
  text "i" at 134.917,215.995 h4.63
  text "n" at 135.804,215.995 h4.63
  text "l" at 137.831,215.995 h4.63
  text "y" at 138.718,215.995 h4.63
  text "n" at 141.336,215.995 h4.63
  text "o" at 143.362,215.995 h4.63
  text "t" at 145.431,215.995 h4.63
  text "p" at 147.627,215.995 h4.63
  text "o" at 149.612,215.995 h4.63
  text "p" at 151.681,215.995 h4.63
  text "u" at 153.708,215.995 h4.63
  text "l" at 155.734,215.995 h4.63
  text "a" at 156.621,215.995 h4.63
  text "t" at 158.479,215.995 h4.63
  text "e" at 159.788,215.995 h4.63
  text "d" at 161.73,215.995 h4.63
  text "." at 163.757,215.995 h4.63
  text "K" at 165.573,215.995 h4.63
  text "n" at 167.6,215.995 h4.63
  text "o" at 169.626,215.995 h4.63
  text "w" at 171.653,215.995 h4.63
  text "i" at 174.44,215.995 h4.63
  text "n" at 175.327,215.995 h4.63
  text "g" at 177.354,215.995 h4.63
  text "t" at 180.056,215.995 h4.63
  text "h" at 181.365,215.995 h4.63
  text "i" at 183.35,215.995 h4.63
  text "s" at 184.236,215.995 h4.63
  text "," at 185.757,215.995 h4.63
  text "w" at 187.614,215.995 h4.63
  text "e" at 190.401,215.995 h4.63
  text "s" at 193.188,215.995 h4.63
  text "h" at 194.708,215.995 h4.63
  text "o" at 196.735,215.995 h4.63
  text "u" at 198.804,215.995 h4.63
  text "l" at 200.831,215.995 h4.63
  text "d" at 201.718,215.995 h4.63
  text "b" at 204.631,215.995 h4.63
  text "e" at 206.658,215.995 h4.63
  text "f" at 209.445,215.995 h4.63
  text "i" at 210.627,215.995 h4.63
  text "n" at 211.514,215.995 h4.63
  text "e" at 213.541,215.995 h4.63
  text "w" at 216.328,215.995 h4.63
  text "i" at 219.114,215.995 h4.63
  text "t" at 220.001,215.995 h4.63
  text "h" at 221.31,215.995 h4.63
  text "t" at 224.224,215.995 h4.63
  text "h" at 225.491,215.995 h4.63
  text "e" at 227.517,215.995 h4.63
  text "c" at 97.928,211.265 h4.63
  text "u" at 99.575,211.265 h4.63
  text "r" at 101.602,211.265 h4.63
  text "r" at 102.953,211.265 h4.63
  text "e" at 104.304,211.265 h4.63
  text "n" at 106.246,211.265 h4.63
  text "t" at 108.273,211.265 h4.63
  text "c" at 110.469,211.265 h4.63
  text "l" at 112.116,211.265 h4.63
  text "e" at 112.96,211.265 h4.63
  text "a" at 114.902,211.265 h4.63
  text "r" at 116.76,211.265 h4.63
  text "a" at 118.112,211.265 h4.63
  text "n" at 119.97,211.265 h4.63
  text "c" at 121.996,211.265 h4.63
  text "e" at 123.643,211.265 h4.63
  text "." at 125.585,211.265 h4.63
  text "I" at 127.443,211.265 h4.63
  text "f" at 128.415,211.265 h4.63
  text "y" at 130.441,211.265 h4.63
  text "o" at 132.173,211.265 h4.63
  text "u" at 134.242,211.265 h4.63
  text "c" at 137.155,211.265 h4.63
  text "a" at 138.802,211.265 h4.63
  text "n" at 140.618,211.265 h4.63
  text "m" at 143.531,211.265 h4.63
  text "o" at 146.614,211.265 h4.63
  text "v" at 148.683,211.265 h4.63
  text "e" at 150.414,211.265 h4.63
  text "C" at 153.243,211.265 h4.63
  text "2" at 155.312,211.265 h4.63
  text "0" at 157.254,211.265 h4.63
  text "/" at 159.197,211.265 h4.63
  text "R" at 160.717,211.265 h4.63
  text "3" at 162.828,211.265 h4.63
  text "9" at 164.771,211.265 h4.63
  text "/" at 166.755,211.265 h4.63
  text "R" at 168.233,211.265 h4.63
  text "4" at 170.344,211.265 h4.63
  text "0" at 172.287,211.265 h4.63
  text "/" at 174.271,211.265 h4.63
  text "R" at 175.749,211.265 h4.63
  text "4" at 177.86,211.265 h4.63
  text "1" at 179.803,211.265 h4.63
  text "o" at 182.632,211.265 h4.63
  text "n" at 184.701,211.265 h4.63
  text "T" at 187.614,211.265 h4.63
  text "O" at 189.515,211.265 h4.63
  text "P" at 192.048,211.265 h4.63
  text "s" at 194.962,211.265 h4.63
  text "i" at 196.482,211.265 h4.63
  text "d" at 197.368,211.265 h4.63
  text "e" at 199.353,211.265 h4.63
  text "," at 201.295,211.265 h4.63
  text "t" at 203.153,211.265 h4.63
  text "h" at 204.462,211.265 h4.63
  text "a" at 206.489,211.265 h4.63
  text "t" at 208.305,211.265 h4.63
  text "w" at 210.501,211.265 h4.63
  text "o" at 213.245,211.265 h4.63
  text "u" at 215.314,211.265 h4.63
  text "l" at 217.341,211.265 h4.63
  text "d" at 218.228,211.265 h4.63
  text "b" at 221.141,211.265 h4.63
  text "e" at 223.168,211.265 h4.63
  text "p" at 225.955,211.265 h4.63
  text "e" at 227.982,211.265 h4.63
  text "r" at 229.924,211.265 h4.63
  text "f" at 231.275,211.265 h4.63
  text "e" at 232.458,211.265 h4.63
  text "c" at 234.4,211.265 h4.63
  text "t" at 236.047,211.265 h4.63
  text "." at 237.356,211.265 h4.63
  text "R" at 97.928,206.536 h4.63
  text "4" at 100.039,206.536 h4.63
  text "2" at 102.024,206.536 h4.63
  text "c" at 104.853,206.536 h4.63
  text "o" at 106.5,206.536 h4.63
  text "u" at 108.569,206.536 h4.63
  text "l" at 110.595,206.536 h4.63
  text "d" at 111.482,206.536 h4.63
  text "a" at 114.396,206.536 h4.63
  text "l" at 116.254,206.536 h4.63
  text "s" at 117.098,206.536 h4.63
  text "o" at 118.618,206.536 h4.63
  text "m" at 121.532,206.536 h4.63
  text "o" at 124.614,206.536 h4.63
  text "v" at 126.641,206.536 h4.63
  text "e" at 128.415,206.536 h4.63
  text "t" at 131.244,206.536 h4.63
  text "o" at 132.51,206.536 h4.63
  text "T" at 135.424,206.536 h4.63
  text "O" at 137.324,206.536 h4.63
  text "P" at 139.858,206.536 h4.63
  text "s" at 142.771,206.536 h4.63
  text "i" at 144.291,206.536 h4.63
  text "d" at 145.178,206.536 h4.63
  text "e" at 147.205,206.536 h4.63
  text "." at 149.147,206.536 h4.63
  text "" at 91.564,201.596 h4.59
  text "C" at 97.928,201.596 h4.63
  text "o" at 99.997,201.596 h4.63
  text "n" at 102.066,201.596 h4.63
  text "c" at 104.093,201.596 h4.63
  text "e" at 105.74,201.596 h4.63
  text "r" at 107.682,201.596 h4.63
  text "n" at 109.033,201.596 h4.63
  text "i" at 111.06,201.596 h4.63
  text "n" at 111.947,201.596 h4.63
  text "g" at 113.974,201.596 h4.63
  text "R" at 116.676,201.596 h4.63
  text "4" at 118.745,201.596 h4.63
  text "8" at 120.73,201.596 h4.63
  text "/" at 122.672,201.596 h4.63
  text "R" at 124.192,201.596 h4.63
  text "4" at 126.261,201.596 h4.63
  text "9" at 128.246,201.596 h4.63
  text "a" at 131.075,201.596 h4.63
  text "n" at 132.933,201.596 h4.63
  text "d" at 134.959,201.596 h4.63
  text "R" at 137.873,201.596 h4.63
  text "7" at 139.942,201.596 h4.63
  text "6" at 141.927,201.596 h4.63
  text "," at 143.911,201.596 h4.63
  text "t" at 145.727,201.596 h4.63
  text "r" at 147.036,201.596 h4.63
  text "y" at 148.387,201.596 h4.63
  text "t" at 151.258,201.596 h4.63
  text "o" at 152.525,201.596 h4.63
  text "m" at 155.438,201.596 h4.63
  text "o" at 158.563,201.596 h4.63
  text "v" at 160.59,201.596 h4.63
  text "e" at 162.363,201.596 h4.63
  text "t" at 165.15,201.596 h4.63
  text "h" at 166.459,201.596 h4.63
  text "e" at 168.486,201.596 h4.63
  text "m" at 170.386,201.596 h4.63
  text "a" at 174.397,201.596 h4.63
  text "s" at 176.255,201.596 h4.63
  text "c" at 178.62,201.596 h4.63
  text "l" at 180.267,201.596 h4.63
  text "o" at 181.153,201.596 h4.63
  text "s" at 183.18,201.596 h4.63
  text "e" at 184.7,201.596 h4.63
  text "a" at 187.529,201.596 h4.63
  text "s" at 189.387,201.596 h4.63
  text "p" at 191.794,201.596 h4.63
  text "o" at 193.779,201.596 h4.63
  text "s" at 195.848,201.596 h4.63
  text "s" at 197.368,201.596 h4.63
  text "i" at 198.888,201.596 h4.63
  text "b" at 199.775,201.596 h4.63
  text "l" at 201.802,201.596 h4.63
  text "e" at 202.688,201.596 h4.63
  text "t" at 205.475,201.596 h4.63
  text "o" at 206.784,201.596 h4.63
  text "J" at 209.698,201.596 h4.63
  text "1" at 210.922,201.596 h4.63
  text "0" at 212.865,201.596 h4.63
  text "f" at 215.736,201.596 h4.63
  text "o" at 216.876,201.596 h4.63
  text "r" at 218.945,201.596 h4.63
  text "i" at 221.183,201.596 h4.63
  text "n" at 222.07,201.596 h4.63
  text "c" at 224.096,201.596 h4.63
  text "r" at 225.701,201.596 h4.63
  text "e" at 227.052,201.596 h4.63
  text "a" at 228.995,201.596 h4.63
  text "s" at 230.853,201.596 h4.63
  text "e" at 232.373,201.596 h4.63
  text "t" at 235.16,201.596 h4.63
  text "h" at 236.468,201.596 h4.63
  text "e" at 238.495,201.596 h4.63
  text "c" at 97.928,196.866 h4.63
  text "l" at 99.575,196.866 h4.63
  text "e" at 100.461,196.866 h4.63
  text "a" at 102.404,196.866 h4.63
  text "r" at 104.262,196.866 h4.63
  text "a" at 105.613,196.866 h4.63
  text "n" at 107.471,196.866 h4.63
  text "c" at 109.498,196.866 h4.63
  text "e" at 111.144,196.866 h4.63
  text "w" at 113.931,196.866 h4.63
  text "i" at 116.718,196.866 h4.63
  text "t" at 117.605,196.866 h4.63
  text "h" at 118.914,196.866 h4.63
  text "J" at 121.827,196.866 h4.63
  text "9" at 123.01,196.866 h4.63
  text "." at 124.994,196.866 h4.63
  text "Y" at 126.852,196.866 h4.63
  text "o" at 128.71,196.866 h4.63
  text "u" at 130.779,196.866 h4.63
  text "w" at 133.693,196.866 h4.63
  text "i" at 136.48,196.866 h4.63
  text "l" at 137.366,196.866 h4.63
  text "l" at 138.253,196.866 h4.63
  text "n" at 139.942,196.866 h4.63
  text "o" at 141.969,196.866 h4.63
  text "t" at 144.038,196.866 h4.63
  text "r" at 146.234,196.866 h4.63
  text "e" at 147.585,196.866 h4.63
  text "a" at 149.485,196.866 h4.63
  text "c" at 151.343,196.866 h4.63
  text "h" at 152.99,196.866 h4.63
  text "5" at 155.903,196.866 h4.63
  text "m" at 157.846,196.866 h4.63
  text "m" at 160.928,196.866 h4.63
  text "," at 164.053,196.866 h4.63
  text "b" at 165.911,196.866 h4.63
  text "u" at 167.937,196.866 h4.63
  text "t" at 169.964,196.866 h4.63
  text "t" at 172.118,196.866 h4.63
  text "r" at 173.427,196.866 h4.63
  text "y" at 174.778,196.866 h4.63
  text "t" at 177.396,196.866 h4.63
  text "o" at 178.663,196.866 h4.63
  text "g" at 181.576,196.866 h4.63
  text "a" at 183.392,196.866 h4.63
  text "i" at 185.25,196.866 h4.63
  text "n" at 186.137,196.866 h4.63
  text "a" at 189.05,196.866 h4.63
  text "s" at 190.908,196.866 h4.63
  text "m" at 193.315,196.866 h4.63
  text "u" at 196.44,196.866 h4.63
  text "c" at 198.466,196.866 h4.63
  text "h" at 200.113,196.866 h4.63
  text "a" at 202.984,196.866 h4.63
  text "s" at 204.842,196.866 h4.63
  text "p" at 207.249,196.866 h4.63
  text "o" at 209.276,196.866 h4.63
  text "s" at 211.303,196.866 h4.63
  text "s" at 212.823,196.866 h4.63
  text "i" at 214.343,196.866 h4.63
  text "b" at 215.23,196.866 h4.63
  text "l" at 217.257,196.866 h4.63
  text "e" at 218.143,196.866 h4.63
  text "." at 220.086,196.866 h4.63
  text "" at 91.564,191.926 h4.59
  text "O" at 97.928,191.926 h4.63
  text "n" at 100.504,191.926 h4.63
  text "t" at 103.417,191.926 h4.63
  text "h" at 104.726,191.926 h4.63
  text "e" at 106.753,191.926 h4.63
  text "o" at 109.54,191.926 h4.63
  text "t" at 111.609,191.926 h4.63
  text "h" at 112.918,191.926 h4.63
  text "e" at 114.945,191.926 h4.63
  text "r" at 116.887,191.926 h4.63
  text "s" at 119.083,191.926 h4.63
  text "i" at 120.603,191.926 h4.63
  text "d" at 121.49,191.926 h4.63
  text "e" at 123.516,191.926 h4.63
  text "o" at 126.303,191.926 h4.63
  text "f" at 128.372,191.926 h4.63
  text "t" at 130.399,191.926 h4.63
  text "h" at 131.708,191.926 h4.63
  text "e" at 133.735,191.926 h4.63
  text "U" at 136.564,191.926 h4.63
  text "S" at 139.055,191.926 h4.63
  text "B" at 140.787,191.926 h4.63
  text "c" at 143.785,191.926 h4.63
  text "o" at 145.431,191.926 h4.63
  text "n" at 147.5,191.926 h4.63
  text "n" at 149.527,191.926 h4.63
  text "e" at 151.554,191.926 h4.63
  text "c" at 153.454,191.926 h4.63
  text "t" at 155.101,191.926 h4.63
  text "o" at 156.368,191.926 h4.63
  text "r" at 158.437,191.926 h4.63
  text "(" at 160.675,191.926 h4.63
  text "J" at 161.857,191.926 h4.63
  text "9" at 163.082,191.926 h4.63
  text ")" at 165.024,191.926 h4.63
  text "," at 166.206,191.926 h4.63
  text "c" at 168.064,191.926 h4.63
  text "o" at 169.669,191.926 h4.63
  text "u" at 171.738,191.926 h4.63
  text "l" at 173.765,191.926 h4.63
  text "d" at 174.651,191.926 h4.63
  text "y" at 177.565,191.926 h4.63
  text "o" at 179.296,191.926 h4.63
  text "u" at 181.365,191.926 h4.63
  text "c" at 184.236,191.926 h4.63
  text "h" at 185.883,191.926 h4.63
  text "e" at 187.91,191.926 h4.63
  text "c" at 189.852,191.926 h4.63
  text "k" at 191.499,191.926 h4.63
  text "h" at 194.117,191.926 h4.63
  text "o" at 196.144,191.926 h4.63
  text "w" at 198.171,191.926 h4.63
  text "t" at 201.844,191.926 h4.63
  text "h" at 203.153,191.926 h4.63
  text "e" at 205.18,191.926 h4.63
  text "s" at 207.967,191.926 h4.63
  text "i" at 209.487,191.926 h4.63
  text "t" at 210.374,191.926 h4.63
  text "u" at 211.683,191.926 h4.63
  text "a" at 213.71,191.926 h4.63
  text "t" at 215.568,191.926 h4.63
  text "i" at 216.877,191.926 h4.63
  text "o" at 217.721,191.926 h4.63
  text "n" at 219.79,191.926 h4.63
  text "w" at 222.704,191.926 h4.63
  text "o" at 225.448,191.926 h4.63
  text "u" at 227.517,191.926 h4.63
  text "l" at 229.544,191.926 h4.63
  text "d" at 230.431,191.926 h4.63
  text "l" at 233.344,191.926 h4.63
  text "o" at 234.231,191.926 h4.63
  text "o" at 236.258,191.926 h4.63
  text "k" at 238.327,191.926 h4.63
  text "l" at 97.928,187.197 h4.63
  text "i" at 98.815,187.197 h4.63
  text "k" at 99.701,187.197 h4.63
  text "e" at 101.475,187.197 h4.63
  text "i" at 104.304,187.197 h4.63
  text "f" at 105.191,187.197 h4.63
  text "w" at 107.217,187.197 h4.63
  text "e" at 110.004,187.197 h4.63
  text "c" at 112.791,187.197 h4.63
  text "h" at 114.438,187.197 h4.63
  text "a" at 116.465,187.197 h4.63
  text "n" at 118.323,187.197 h4.63
  text "g" at 120.35,187.197 h4.63
  text "e" at 122.165,187.197 h4.63
  text "L" at 124.994,187.197 h4.63
  text "8" at 126.599,187.197 h4.63
  text "/" at 128.583,187.197 h4.63
  text "L" at 130.061,187.197 h4.63
  text "9" at 131.708,187.197 h4.63
  text "/" at 133.651,187.197 h4.63
  text "L" at 135.171,187.197 h4.63
  text "1" at 136.775,187.197 h4.63
  text "2" at 138.718,187.197 h4.63
  text "a" at 141.754,187.197 h4.63
  text "n" at 143.612,187.197 h4.63
  text "d" at 145.639,187.197 h4.63
  text "L" at 148.553,187.197 h4.63
  text "1" at 150.199,187.197 h4.63
  text "3" at 152.142,187.197 h4.63
  text "f" at 155.013,187.197 h4.63
  text "r" at 156.195,187.197 h4.63
  text "o" at 157.504,187.197 h4.63
  text "m" at 159.531,187.197 h4.63
  text "0" at 163.543,187.197 h4.63
  text "8" at 165.485,187.197 h4.63
  text "0" at 167.47,187.197 h4.63
  text "5" at 169.412,187.197 h4.63
  text "t" at 172.241,187.197 h4.63
  text "o" at 173.55,187.197 h4.63
  text "0" at 176.464,187.197 h4.63
  text "4" at 178.406,187.197 h4.63
  text "0" at 180.39,187.197 h4.63
  text "2" at 182.333,187.197 h4.63
  text "p" at 185.204,187.197 h4.63
  text "a" at 187.231,187.197 h4.63
  text "c" at 189.089,187.197 h4.63
  text "k" at 190.736,187.197 h4.63
  text "a" at 192.509,187.197 h4.63
  text "g" at 194.367,187.197 h4.63
  text "e" at 196.141,187.197 h4.63
  text "s" at 198.083,187.197 h4.63
  text "?" at 199.603,187.197 h4.63
  text "I" at 202.263,187.197 h4.63
  text "h" at 204.121,187.197 h4.63
  text "a" at 206.148,187.197 h4.63
  text "v" at 208.006,187.197 h4.63
  text "e" at 209.737,187.197 h4.63
  text "f" at 212.566,187.197 h4.63
  text "o" at 213.706,187.197 h4.63
  text "u" at 215.775,187.197 h4.63
  text "n" at 217.802,187.197 h4.63
  text "d" at 219.829,187.197 h4.63
  text "s" at 222.742,187.197 h4.63
  text "o" at 224.22,187.197 h4.63
  text "m" at 226.289,187.197 h4.63
  text "e" at 229.372,187.197 h4.63
  text "0" at 232.159,187.197 h4.63
  text "4" at 234.143,187.197 h4.63
  text "0" at 236.086,187.197 h4.63
  text "2" at 238.07,187.197 h4.63
  text "f" at 97.928,182.51 h4.63
  text "e" at 99.11,182.51 h4.63
  text "r" at 101.053,182.51 h4.63
  text "r" at 102.404,182.51 h4.63
  text "i" at 103.755,182.51 h4.63
  text "t" at 104.642,182.51 h4.63
  text "e" at 105.951,182.51 h4.63
  text "b" at 108.78,182.51 h4.63
  text "e" at 110.764,182.51 h4.63
  text "a" at 112.707,182.51 h4.63
  text "d" at 114.565,182.51 h4.63
  text "s" at 116.591,182.51 h4.63
  text "2" at 118.956,182.51 h4.63
  text "2" at 120.941,182.51 h4.63
  text "0" at 122.883,182.51 h4.63
  text "O" at 124.868,182.51 h4.63
  text "h" at 127.443,182.51 h4.63
  text "m" at 129.47,182.51 h4.63
  text "s" at 132.553,182.51 h4.63
  text "/" at 134.959,182.51 h4.63
  text "1" at 137.324,182.51 h4.63
  text "A" at 139.266,182.51 h4.63
  text "." at 141.504,182.51 h4.63
  text "W" at 143.362,182.51 h4.63
  text "e" at 146.825,182.51 h4.63
  text "d" at 149.654,182.51 h4.63
  text "o" at 151.638,182.51 h4.63
  text "n" at 153.708,182.51 h4.63
  text "" at 155.734,182.51 h4.63
  text "t" at 156.706,182.51 h4.63
  text "n" at 158.901,182.51 h4.63
  text "e" at 160.928,182.51 h4.63
  text "e" at 162.828,182.51 h4.63
  text "d" at 164.771,182.51 h4.63
  text "t" at 167.684,182.51 h4.63
  text "h" at 168.993,182.51 h4.63
  text "e" at 171.02,182.51 h4.63
  text "2" at 173.807,182.51 h4.63
  text "A" at 175.791,182.51 h4.63
  text "h" at 178.916,182.51 h4.63
  text "e" at 180.901,182.51 h4.63
  text "r" at 182.843,182.51 h4.63
  text "e" at 184.194,182.51 h4.63
  text "r" at 187.023,182.51 h4.63
  text "e" at 188.332,182.51 h4.63
  text "a" at 190.275,182.51 h4.63
  text "l" at 192.133,182.51 h4.63
  text "l" at 193.019,182.51 h4.63
  text "y" at 193.906,182.51 h4.63
  text "." at 195.679,182.51 h4.63
  text "I" at 85.2,173.051 h4.63
  text "d" at 87.058,173.051 h4.63
  text "o" at 89.085,173.051 h4.63
  text "n" at 91.154,173.051 h4.63
  text "" at 93.181,173.051 h4.63
  text "t" at 94.152,173.051 h4.63
  text "k" at 96.305,173.051 h4.63
  text "n" at 98.079,173.051 h4.63
  text "o" at 100.106,173.051 h4.63
  text "w" at 102.175,173.051 h4.63
  text "i" at 105.806,173.051 h4.63
  text "f" at 106.693,173.051 h4.63
  text "t" at 108.762,173.051 h4.63
  text "h" at 110.071,173.051 h4.63
  text "e" at 112.055,173.051 h4.63
  text "r" at 114.884,173.051 h4.63
  text "e" at 116.236,173.051 h4.63
  text "c" at 118.178,173.051 h4.63
  text "o" at 119.783,173.051 h4.63
  text "m" at 121.809,173.051 h4.63
  text "m" at 124.892,173.051 h4.63
  text "e" at 127.974,173.051 h4.63
  text "n" at 129.917,173.051 h4.63
  text "d" at 131.943,173.051 h4.63
  text "a" at 133.97,173.051 h4.63
  text "t" at 135.828,173.051 h4.63
  text "i" at 137.137,173.051 h4.63
  text "o" at 138.024,173.051 h4.63
  text "n" at 140.093,173.051 h4.63
  text "s" at 142.12,173.051 h4.63
  text "a" at 144.527,173.051 h4.63
  text "b" at 146.384,173.051 h4.63
  text "o" at 148.369,173.051 h4.63
  text "v" at 150.438,173.051 h4.63
  text "e" at 152.169,173.051 h4.63
  text "a" at 154.998,173.051 h4.63
  text "r" at 156.856,173.051 h4.63
  text "e" at 158.165,173.051 h4.63
  text "s" at 160.994,173.051 h4.63
  text "u" at 162.515,173.051 h4.63
  text "f" at 164.541,173.051 h4.63
  text "f" at 165.724,173.051 h4.63
  text "i" at 166.906,173.051 h4.63
  text "c" at 167.793,173.051 h4.63
  text "i" at 169.439,173.051 h4.63
  text "e" at 170.284,173.051 h4.63
  text "n" at 172.226,173.051 h4.63
  text "t" at 174.253,173.051 h4.63
  text "." at 175.562,173.051 h4.63
  text "T" at 177.42,173.051 h4.63
  text "r" at 179.32,173.051 h4.63
  text "y" at 180.629,173.051 h4.63
  text "t" at 183.289,173.051 h4.63
  text "o" at 184.556,173.051 h4.63
  text "u" at 187.512,173.051 h4.63
  text "p" at 189.539,173.051 h4.63
  text "d" at 191.565,173.051 h4.63
  text "a" at 193.592,173.051 h4.63
  text "t" at 195.45,173.051 h4.63
  text "e" at 196.759,173.051 h4.63
  text "t" at 199.546,173.051 h4.63
  text "h" at 200.855,173.051 h4.63
  text "e" at 202.882,173.051 h4.63
  text "d" at 205.711,173.051 h4.63
  text "e" at 207.696,173.051 h4.63
  text "s" at 209.638,173.051 h4.63
  text "i" at 211.158,173.051 h4.63
  text "g" at 212.003,173.051 h4.63
  text "n" at 213.818,173.051 h4.63
  text "a" at 216.732,173.051 h4.63
  text "n" at 218.59,173.051 h4.63
  text "d" at 220.616,173.051 h4.63
  text "I" at 223.53,173.051 h4.63
  text "" at 224.501,173.051 h4.63
  text "l" at 225.472,173.051 h4.63
  text "l" at 226.359,173.051 h4.63
  text "d" at 228.133,173.051 h4.63
  text "i" at 230.159,173.051 h4.63
  text "s" at 231.046,173.051 h4.63
  text "c" at 232.566,173.051 h4.63
  text "u" at 234.213,173.051 h4.63
  text "s" at 236.24,173.051 h4.63
  text "s" at 237.76,173.051 h4.63
  text "i" at 85.2,168.322 h4.63
  text "t" at 86.087,168.322 h4.63
  text "w" at 88.282,168.322 h4.63
  text "i" at 91.069,168.322 h4.63
  text "t" at 91.956,168.322 h4.63
  text "h" at 93.265,168.322 h4.63
  text "o" at 96.136,168.322 h4.63
  text "u" at 98.205,168.322 h4.63
  text "r" at 100.232,168.322 h4.63
  text "p" at 102.47,168.322 h4.63
  text "r" at 104.497,168.322 h4.63
  text "o" at 105.806,168.322 h4.63
  text "d" at 107.875,168.322 h4.63
  text "u" at 109.902,168.322 h4.63
  text "c" at 111.929,168.322 h4.63
  text "t" at 113.575,168.322 h4.63
  text "i" at 114.884,168.322 h4.63
  text "o" at 115.729,168.322 h4.63
  text "n" at 117.798,168.322 h4.63
  text "t" at 120.711,168.322 h4.63
  text "e" at 122.02,168.322 h4.63
  text "a" at 123.963,168.322 h4.63
  text "m" at 125.779,168.322 h4.63
  text "l" at 129.79,168.322 h4.63
  text "a" at 130.677,168.322 h4.63
  text "t" at 132.535,168.322 h4.63
  text "e" at 133.801,168.322 h4.63
  text "r" at 135.744,168.322 h4.63
  text "t" at 138.233,168.322 h4.63
  text "o" at 139.5,168.322 h4.63
  text "n" at 141.569,168.322 h4.63
  text "i" at 143.596,168.322 h4.63
  text "g" at 144.482,168.322 h4.63
  text "h" at 146.298,168.322 h4.63
  text "t" at 148.325,168.322 h4.63
  text "." at 149.634,168.322 h4.63
  text "W" at 85.2,163.593 h4.63
  text "h" at 88.662,163.593 h4.63
  text "e" at 90.689,163.593 h4.63
  text "r" at 92.632,163.593 h4.63
  text "e" at 93.983,163.593 h4.63
  text "t" at 96.77,163.593 h4.63
  text "h" at 98.079,163.593 h4.63
  text "e" at 100.106,163.593 h4.63
  text "s" at 102.935,163.593 h4.63
  text "i" at 104.455,163.593 h4.63
  text "t" at 105.299,163.593 h4.63
  text "u" at 106.608,163.593 h4.63
  text "a" at 108.635,163.593 h4.63
  text "t" at 110.493,163.593 h4.63
  text "i" at 111.802,163.593 h4.63
  text "o" at 112.689,163.593 h4.63
  text "n" at 114.758,163.593 h4.63
  text "i" at 117.629,163.593 h4.63
  text "s" at 118.516,163.593 h4.63
  text "i" at 120.923,163.593 h4.63
  text "m" at 121.767,163.593 h4.63
  text "p" at 124.892,163.593 h4.63
  text "o" at 126.919,163.593 h4.63
  text "s" at 128.988,163.593 h4.63
  text "s" at 130.508,163.593 h4.63
  text "i" at 132.028,163.593 h4.63
  text "b" at 132.915,163.593 h4.63
  text "l" at 134.941,163.593 h4.63
  text "e" at 135.828,163.593 h4.63
  text "t" at 138.615,163.593 h4.63
  text "o" at 139.924,163.593 h4.63
  text "i" at 142.838,163.593 h4.63
  text "m" at 143.724,163.593 h4.63
  text "p" at 146.849,163.593 h4.63
  text "r" at 148.876,163.593 h4.63
  text "o" at 150.185,163.593 h4.63
  text "v" at 152.254,163.593 h4.63
  text "e" at 153.985,163.593 h4.63
  text "," at 155.927,163.593 h4.63
  text "I" at 157.785,163.593 h4.63
  text "t" at 159.601,163.593 h4.63
  text "h" at 160.91,163.593 h4.63
  text "i" at 162.937,163.593 h4.63
  text "n" at 163.823,163.593 h4.63
  text "k" at 165.85,163.593 h4.63
  text "w" at 168.468,163.593 h4.63
  text "e" at 171.255,163.593 h4.63
  text "c" at 174.084,163.593 h4.63
  text "a" at 175.731,163.593 h4.63
  text "n" at 177.589,163.593 h4.63
  text "d" at 180.46,163.593 h4.63
  text "i" at 182.487,163.593 h4.63
  text "s" at 183.374,163.593 h4.63
  text "c" at 184.894,163.593 h4.63
  text "u" at 186.541,163.593 h4.63
  text "s" at 188.568,163.593 h4.63
  text "s" at 190.088,163.593 h4.63
  text "a" at 192.494,163.593 h4.63
  text "b" at 194.352,163.593 h4.63
  text "o" at 196.337,163.593 h4.63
